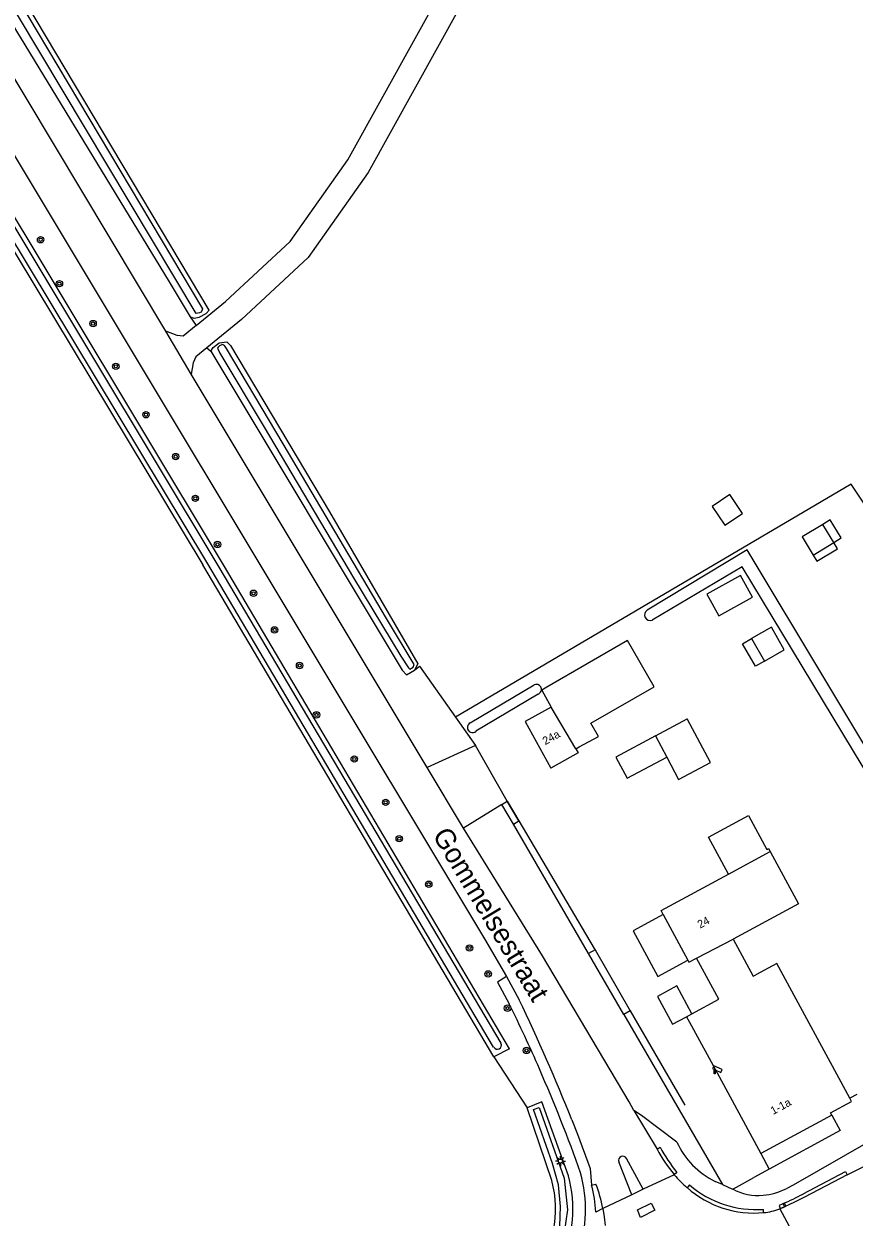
# Model space of a CAD drawing. Extents: x 137000 to 140001, y 403500 to 406000.
# Drawn here: x 139469.8 to 139573.5, y 403918.5 to 404067.6 of the extents above; entities that cross this region are included whole.
import ezdxf

# ---------------------------------------------------------------- set-up
doc = ezdxf.new("R2010")
doc.units = 0
for name, color, linetype in [('gg-afsc-draadraster', 7, 'Continuous'), ('gg-afsc-erfafscheiding', 7, 'Continuous'), ('gg-afsc-hekwerk', 7, 'Continuous'), ('gg-anno-huisnummerreeks BGT', 7, 'Continuous'), ('gg-anno-openbare ruimte label', 7, 'Continuous'), ('gg-bbg-bijgebouw', 7, 'Continuous'), ('gg-bbg-gedigitaliseerde bebouwing', 7, 'Continuous'), ('gg-bbg-gedigitaliseerde bijgebouw', 7, 'Continuous'), ('gg-bbg-hoofdgebouw', 7, 'Continuous'), ('gg-bbg-luifel en loopbrug', 7, 'Continuous'), ('gg-bbg-tussenscheiding', 7, 'Continuous'), ('gg-knt-bronhoudergrens', 7, 'Continuous'), ('gg-knt-onverhard', 7, 'Continuous'), ('gg-knt-verharding', 7, 'Continuous'), ('gg-knt-verharding nz', 7, 'Continuous'), ('gg-kntw-bovenkant insteek waterloop', 7, 'Continuous'), ('gg-kntw-waterlijn', 7, 'Continuous'), ('gt-grn-groengrens NZ', 7, 'Continuous'), ('gt-grn-weggrens', 7, 'Continuous'), ('gt-symb-boom', 7, 'Continuous'), ('gt-symb-camera', 7, 'Continuous'), ('gt-symb-kolk', 7, 'Continuous'), ('gt-symb-lichtmast', 7, 'Continuous')]:
    doc.layers.add(name, color=color, linetype=linetype)

# ---------------------------------------------------------------- blocks, each defined once
blk = doc.blocks.new('gt0-BOOM')
at = {"layer": 'gt-symb-boom'}
for radius in [0.4, 0.2]:
    blk.add_circle((0, 0), radius, dxfattribs=at)
blk = doc.blocks.new('gt0-CAMERA')
at = {"layer": 'gt-symb-camera'}
for points in [[(0.07, 0.48), (0.75, 0.16), (0.92, 0.51), (-0.12, 1), (-0.28, 0.65), (-0.07, 0.55)], [(0.07, 0.48), (0.07, 0), (-0.07, 0), (-0.07, 0.55)]]:
    blk.add_lwpolyline(points, dxfattribs=at)
blk = doc.blocks.new('gt0-KOLK')
at = {"layer": 'gt-symb-kolk'}
blk.add_lwpolyline([(0, 0), (0.37, 0), (0.37, 0.4), (-0.38, 0.4), (-0.38, 0), (0, 0)], dxfattribs=at)
blk = doc.blocks.new('gt0-LMAST')
at = {"layer": 'gt-symb-lichtmast'}
for p, q in [((-0.18, 0.17), (-0.45, 0.44)), ((-0.01, 0.25), (-0.01, 0.62)), ((0.17, 0.17), (0.44, 0.44)), ((-0.26, 0), (-0.63, 0)), ((-0.18, -0.18), (-0.45, -0.45)), ((-0.01, -0.25), (-0.01, -0.63)), ((0.44, -0.45), (0.17, -0.18)), ((0.24, 0), (0.62, 0))]:
    blk.add_line(p, q, dxfattribs=at)
blk.add_circle((-0.01, 0), 0.25, dxfattribs=at)

msp = doc.modelspace()

# ---------------------------------------------------------------- linework, layer by layer
at = {"layer": 'gg-afsc-draadraster'}
msp.add_lwpolyline([(139577.76, 404003.1), (139573.16, 404010.07), (139523.72, 403980.95)], dxfattribs=at)
at = {"layer": 'gg-afsc-erfafscheiding'}
for p, q in [((139519.2, 403987.33), (139523.72, 403980.95)), ((139523.72, 403980.95), (139526.22, 403977.43)), ((139530.15, 403970.45), (139526.22, 403977.43)), ((139531.61, 403967.99), (139541.05, 403952.04)), ((139541.05, 403952.04), (139541.15, 403951.87)), ((139541.15, 403951.87), (139545.54, 403944.26)), ((139545.54, 403944.26), (139544.75, 403943.83)), ((139573.85, 403933.81), (139572.98, 403933.36)), ((139558.8, 403922.26), (139560.98, 403923.44)), ((139562.9, 403924.51), (139560.98, 403923.44)), ((139558.33, 403922.01), (139558.8, 403922.26))]:
    msp.add_line(p, q, dxfattribs=at)
at = {"layer": 'gg-afsc-hekwerk'}
for p, q in [((139530.15, 403970.45), (139531.61, 403967.99)), ((139531.61, 403967.99), (139541.05, 403952.04)), ((139541.05, 403952.04), (139541.15, 403951.87)), ((139541.15, 403951.87), (139545.54, 403944.26)), ((139545.54, 403944.26), (139552.38, 403932.47)), ((139558.8, 403922.26), (139560.98, 403923.44))]:
    msp.add_line(p, q, dxfattribs=at)
at = {"layer": 'gg-bbg-bijgebouw'}
for q in [(139552.66, 403980.73), (139550.11, 403975.96)]:
    msp.add_line((139548.69, 403978.61), q, dxfattribs=at)
for points in [[(139538.73, 403977.01), (139539.17, 403977.25), (139541.56, 403978.55), (139540.61, 403980.2), (139548.51, 403984.75), (139545.19, 403990.51), (139535.11, 403984.71), (139534.47, 403984.34), (139535.65, 403982.21)], [(139550.11, 403975.96), (139551.59, 403973.18), (139555.56, 403975.3), (139552.66, 403980.73)]]:
    msp.add_lwpolyline(points, dxfattribs=at)
at = {"layer": 'gg-bbg-gedigitaliseerde bebouwing'}
msp.add_line((139557.8, 403961.34), (139563.02, 403964.17), dxfattribs=at)
at = {"layer": 'gg-bbg-gedigitaliseerde bijgebouw'}
for p, q in [((139570.97, 404002.78), (139569.59, 404005.04)), ((139568.38, 404001.21), (139570.97, 404002.78)), ((139560.68, 403990.76), (139562.3, 403987.94)), ((139562.3, 403987.94), (139564.79, 403989.37))]:
    msp.add_line(p, q, dxfattribs=at)
for points in [[(139569.59, 404005.04), (139567.01, 404003.47), (139568.38, 404001.21)], [(139560.82, 403995.95), (139559.3, 403998.66), (139555.11, 403996.32), (139556.62, 403993.6), (139560.82, 403995.95)], [(139564.79, 403989.37), (139563.18, 403992.18), (139560.68, 403990.76)]]:
    msp.add_lwpolyline(points, dxfattribs=at)
at = {"layer": 'gg-bbg-hoofdgebouw'}
for p, q in [((139549.65, 403956.3), (139552.74, 403950.58)), ((139552.59, 403943.54), (139553.24, 403943.89)), ((139556.65, 403936.05), (139561.85, 403926.44)), ((139570.73, 403931.25), (139561.85, 403926.44))]:
    msp.add_line(p, q, dxfattribs=at)
for points in [[(139535.65, 403982.21), (139532.39, 403980.41), (139535.6, 403974.6)], [(139538.73, 403977.01), (139539.02, 403976.48), (139535.6, 403974.6)], [(139563.02, 403964.17), (139566.55, 403957.63), (139558.42, 403953.22)], [(139549.65, 403956.3), (139549.39, 403956.79), (139557.8, 403961.34)], [(139558.42, 403953.22), (139560.92, 403948.61), (139561.22, 403948.78)], [(139552.74, 403950.58), (139552.88, 403950.33), (139553.84, 403950.85)], [(139553.24, 403943.89), (139556.61, 403945.72), (139553.84, 403950.85)], [(139572.98, 403933.36), (139563.86, 403950.2), (139561.22, 403948.78)], [(139552.59, 403943.54), (139552.95, 403942.87), (139556.65, 403936.05)], [(139570.73, 403931.25), (139570.58, 403931.54), (139573.2, 403932.96), (139572.98, 403933.36)]]:
    msp.add_lwpolyline(points, dxfattribs=at)
at = {"layer": 'gg-bbg-luifel en loopbrug'}
msp.add_line((139561.85, 403926.44), (139562.9, 403924.51), dxfattribs=at)
for points in [[(139557.99, 404008.76), (139555.79, 404007.28), (139557.36, 404004.93), (139559.57, 404006.41), (139557.99, 404008.76)], [(139570.97, 404002.78), (139571.89, 404003.34), (139570.52, 404005.6), (139569.59, 404005.04)], [(139568.38, 404001.21), (139568.85, 404000.43), (139571.44, 404002), (139570.97, 404002.78)], [(139562.3, 403987.94), (139561.19, 403987.31), (139559.58, 403990.12), (139560.68, 403990.76)], [(139548.69, 403978.61), (139543.75, 403975.97), (139545.17, 403973.32), (139550.11, 403975.96)], [(139557.8, 403961.34), (139555.31, 403965.95), (139560.33, 403968.67), (139562.61, 403964.44), (139562.81, 403964.55), (139563.02, 403964.17)], [(139549.65, 403956.3), (139545.89, 403954.26), (139548.98, 403948.54), (139552.74, 403950.58)], [(139553.24, 403943.89), (139551.35, 403947.38), (139548.94, 403946.08), (139550.83, 403942.59), (139552.59, 403943.54)], [(139570.73, 403931.25), (139571.78, 403929.31), (139562.9, 403924.51)]]:
    msp.add_lwpolyline(points, dxfattribs=at)
at = {"layer": 'gg-bbg-tussenscheiding'}
for p, q in [((139538.73, 403977.01), (139535.65, 403982.21)), ((139553.84, 403950.85), (139558.42, 403953.22))]:
    msp.add_line(p, q, dxfattribs=at)
at = {"layer": 'gg-knt-bronhoudergrens'}
msp.add_line((139528.48, 403938.53), (139532.66, 403932.17), dxfattribs=at)
at = {"layer": 'gg-knt-onverhard'}
for points in [[(139491.29, 404029.87), (139494.97, 404032.89), (139503.02, 404040.36), (139510.26, 404050.58), (139527.49, 404081.69), (139540.58, 404106.68), (139553.04, 404125.36), (139568.03, 404138.11), (139589.58, 404152.78), (139603.6, 404158.75), (139631.51, 404167.9), (139632.52, 404165.07), (139604.66, 404155.94), (139589.5, 404149.48), (139589.47, 404144.47), (139591.17, 404139.97), (139612.78, 404114.78), (139639.17, 404074.78), (139665.44, 404031.24), (139674.74, 404017.1), (139677, 404013.66), (139684.57, 404000.24)], [(139672.1, 404015.65), (139662.9, 404029.64), (139636.63, 404073.18), (139610.38, 404112.97), (139588.9, 404138.01), (139584.48, 404139.45), (139577.11, 404140.66), (139569.85, 404135.72), (139555.3, 404123.34), (139543.16, 404105.15), (139530.13, 404080.27), (139512.8, 404048.98), (139505.28, 404038.37), (139496.94, 404030.62), (139492.61, 404027.08)], [(139491.29, 404029.87), (139489.68, 404028.56), (139488.93, 404028.61), (139487.48, 404029.17)], [(139492.61, 404027.08), (139491.25, 404025.97), (139490.9, 404025.22), (139490.68, 404023.82)]]:
    msp.add_lwpolyline(points, dxfattribs=at)
at = {"layer": 'gg-knt-verharding'}
for p, q in [((139487.48, 404029.17), (139381.92, 404205.17)), ((139520.18, 403974.65), (139490.68, 404023.82)), ((139524.71, 403967.09), (139520.18, 403974.65)), ((139529.48, 403970.06), (139524.71, 403967.09)), ((139529.48, 403970.06), (139530.15, 403970.45)), ((139530.93, 403967.59), (139529.48, 403970.06)), ((139531.61, 403967.99), (139530.15, 403970.45)), ((139530.93, 403967.59), (139531.61, 403967.99)), ((139540.34, 403951.45), (139530.93, 403967.59)), ((139544.75, 403943.83), (139540.34, 403951.45)), ((139530.08, 403948.55), (139531.66, 403945.65)), ((139544.75, 403943.83), (139557.06, 403922.57)), ((139545.97, 403931.83), (139548.89, 403927)), ((139548.89, 403927), (139549.27, 403927.23)), ((139545.72, 403921.3), (139544.12, 403925.4)), ((139547.16, 403922), (139545.08, 403925.82)), ((139551.37, 403924.09), (139551.04, 403923.8)), ((139540.7, 403922.48), (139541.25, 403922.62)), ((139547.16, 403922), (139545.72, 403921.3)), ((139552.94, 403922.52), (139552.67, 403922.18)), ((139557.06, 403922.57), (139556.17, 403922.95)), ((139557.06, 403922.57), (139558.33, 403922.01)), ((139564.62, 403920.19), (139564.81, 403919.79)), ((139542.11, 403919.57), (139541.25, 403919.14)), ((139562.21, 403919.07), (139562.2, 403919.47)), ((139564.81, 403919.79), (139564.23, 403919.54))]:
    msp.add_line(p, q, dxfattribs=at)
for points in [[(139456.55, 404071.12), (139527.32, 403953.26), (139530.08, 403948.55)], [(139530.08, 403948.55), (139528.95, 403947.86), (139530.42, 403945.16)], [(139572.65, 403923.79), (139576.85, 403925.9), (139587.84, 403931.5), (139601.46, 403939.44)], [(139538.23, 403930.64), (139538.93, 403928.86), (139540.52, 403924.57), (139540.7, 403922.48)], [(139551.36, 403927.87), (139546.93, 403931.19), (139545.97, 403931.83)], [(139579.88, 403930.54), (139575.57, 403928.04), (139565.89, 403922.48), (139565.01, 403922.05)], [(139572.65, 403923.79), (139567.31, 403920.98), (139566.08, 403920.35), (139564.81, 403919.79)], [(139567.14, 403921.39), (139572.45, 403924.19), (139572.65, 403923.79)], [(139546.81, 403918.45), (139546.44, 403919.43), (139548.14, 403920.23), (139548.62, 403919.36), (139546.81, 403918.45)], [(139542.11, 403919.57), (139542.28, 403918.52), (139542.39, 403917.46)]]:
    msp.add_lwpolyline(points, dxfattribs=at)
for centre, radius, start, end in [((139331.39, 403848.96), 222.39, 21.5499, 25.7713), ((139348.32, 403855.73), 202.87, 23.6188, 26.1552), ((139348.25, 403855.68), 202.95, 19.6849, 23.6235), ((139560.62, 403932.12), 10.19, 204.6309, 244.1091), ((139544.61, 403925.59), 0.524, 26.6523, 201.2394), ((139564.89, 403935.44), 18.09, 207.8079, 220.0261), ((139568.68, 403937.93), 22.16, 208.8658, 218.6489), ((139522.57, 403919.43), 17.39, 341.4807, 15.3768), ((139560.41, 403931.58), 12.18, 219.6864, 230.5249), ((139523.16, 403917.9), 18.13, 3.9141, 14.6495), ((139523.83, 403916.09), 18.61, 10.7874, 20.557), ((139561.04, 403931.64), 12.63, 228.4998, 275.3344), ((139561.28, 403932.23), 12.79, 229.3579, 274.1255), ((139561.59, 403928.14), 6.94, 241.9551, 274.7482), ((139561.31, 403929.51), 8.33, 275.8731, 296.3892), ((139555.52, 403942.57), 24.16, 292.1209, 298.7547), ((139561.73, 403925.62), 6.57, 274.1831, 292.377)]:
    msp.add_arc(centre, radius, start, end, dxfattribs=at)
at = {"layer": 'gg-knt-verharding nz'}
msp.add_lwpolyline([(139545.97, 403931.83), (139545.39, 403932.92), (139534.58, 403951.15), (139524.71, 403967.09)], dxfattribs=at)
at = {"layer": 'gg-kntw-bovenkant insteek waterloop'}
for p, q in [((139452.67, 404065.45), (139492.11, 404000)), ((139528.48, 403938.53), (139492.11, 404000)), ((139525.55, 403980.26), (139533.53, 403984.99)), ((139534.02, 403983.83), (139526.26, 403979.19)), ((139530.47, 403939.54), (139528.48, 403938.53)), ((139535.73, 403923.08), (139532.66, 403932.17))]:
    msp.add_line(p, q, dxfattribs=at)
for points in [[(139386.87, 404206.06), (139386.78, 404206), (139386.25, 404205.41), (139386.17, 404204.42), (139417.02, 404153.17), (139447.37, 404101.81), (139487.93, 404035.35), (139490.55, 404030.97)], [(139490.55, 404030.97), (139491.02, 404030.78), (139491.65, 404030.91), (139492.52, 404031.39), (139492.92, 404031.81), (139456.9, 404092.22)], [(139530.47, 403939.54), (139494.69, 404000), (139454.45, 404066.89)], [(139493.12, 404026.68), (139493.4, 404027.11), (139494.18, 404027.72), (139495.12, 404027.82), (139495.57, 404027.36), (139507.95, 404006.6), (139518.99, 403987.61), (139518.59, 403986.83)], [(139493.12, 404026.68), (139517.04, 403986.82), (139517.59, 403986.25), (139518.59, 403986.83)], [(139579.69, 403969.33), (139560.14, 404001.85), (139547.64, 403994.32)], [(139578.38, 403968.51), (139559.51, 403999.74), (139548.3, 403993.09)], [(139537.82, 403923.65), (139534.51, 403932.92), (139532.66, 403932.17)]]:
    msp.add_lwpolyline(points, dxfattribs=at)
for centre, radius, start, end in [((139548.03, 403993.73), 0.701, 123.8563, 292.6895), ((139533.81, 403984.42), 0.633, 30.014, 116.7011), ((139533.81, 403984.43), 0.632, 289.3588, 29.8188), ((139525.83, 403979.67), 0.649, 115.7437, 311.933), ((139522.52, 403919.48), 15.86, 335.0938, 15.2399), ((139522.52, 403919.48), 13.69, 322.3178, 15.2373)]:
    msp.add_arc(centre, radius, start, end, dxfattribs=at)
at = {"layer": 'gg-kntw-waterlijn'}
for points in [[(139388.79, 404205.11), (139388.51, 404204.55), (139394.25, 404195.63), (139415.86, 404159.33), (139426.22, 404142.34), (139446.98, 404107.72), (139471.44, 404066.61), (139492.1, 404031.98), (139492.05, 404031.82), (139491.91, 404031.55), (139491.71, 404031.45), (139491.27, 404031.39), (139452.28, 404096.48), (139445.13, 404108.88), (139419.89, 404150.83), (139413.42, 404161.09)], [(139528.47, 403939.74), (139492.63, 404000.31), (139453.53, 404065.14)], [(139529.39, 403940.21), (139494.18, 403999.69), (139454.45, 404065.68)], [(139494.59, 404027.49), (139494.21, 404027.35), (139494.03, 404027.19), (139493.95, 404027.03), (139494.25, 404026.43), (139499.79, 404017.18), (139510.96, 403998.37), (139516.85, 403988.59), (139517.82, 403987.1), (139517.99, 403986.93), (139518.43, 403987.2), (139518.55, 403987.55), (139515.06, 403993.29), (139502.18, 404015.09), (139495.07, 404027.01), (139494.82, 404027.38), (139494.59, 404027.49)], [(139499.5, 403891.1), (139509.03, 403895.84), (139530.08, 403907.47), (139532.22, 403908.97), (139534.39, 403911.34), (139536, 403914.63), (139536.73, 403917.39), (139536.83, 403919.83), (139536.59, 403922.54), (139535.83, 403925.19), (139533.45, 403931.96), (139534.16, 403932.21), (139537.27, 403923.38), (139537.68, 403919.4), (139537.3, 403916.6), (139536.63, 403914.07), (139534.98, 403910.73), (139532.95, 403908.4), (139525.18, 403903.79), (139509.94, 403895.55), (139499.83, 403890.32), (139499.5, 403891.1)]]:
    msp.add_lwpolyline(points, dxfattribs=at)
msp.add_arc((139528.93, 403939.98), 0.511, 206.9892, 26.8424, dxfattribs=at)
at = {"layer": 'gt-grn-groengrens NZ'}
for p, q in [((139490.55, 404030.97), (139491.29, 404029.87)), ((139492.61, 404027.08), (139493.12, 404026.68)), ((139518.59, 403986.83), (139519.2, 403987.33)), ((139541.15, 403951.87), (139540.34, 403951.45))]:
    msp.add_line(p, q, dxfattribs=at)
at = {"layer": 'gt-grn-weggrens'}
for p, q in [((139490.68, 404023.82), (139487.48, 404029.17)), ((139526.22, 403977.43), (139520.18, 403974.65)), ((139551.04, 403923.8), (139547.16, 403922)), ((139545.72, 403921.3), (139542.11, 403919.57)), ((139564.23, 403919.54), (139565.99, 403916.28))]:
    msp.add_line(p, q, dxfattribs=at)

# ---------------------------------------------------------------- block references
at = {"layer": 'gt-symb-boom'}
for p in [(139471.85, 404040.59), (139474.2, 404035.1), (139478.41, 404030.12), (139481.25, 404024.78), (139485.02, 404018.73), (139488.73, 404013.51), (139491.19, 404008.29), (139493.96, 404002.53), (139498.46, 403996.43), (139501.09, 403991.85), (139504.21, 403987.41), (139506.33, 403981.24), (139511.05, 403975.73), (139514.98, 403970.32), (139516.67, 403965.77), (139520.36, 403960.08), (139525.45, 403952.12), (139527.78, 403948.88), (139530.2, 403944.6), (139532.57, 403939.32)]:
    msp.add_blockref('gt0-BOOM', p, dxfattribs=at)
at = {"layer": 'gt-symb-camera'}
msp.add_blockref('gt0-CAMERA', (139556.1, 403936.42), dxfattribs=at)
at = {"layer": 'gt-symb-kolk', "rotation": 23.015280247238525}
msp.add_blockref('gt0-KOLK', (139564.64, 403919.72), dxfattribs=at)
at = {"layer": 'gt-symb-lichtmast'}
msp.add_blockref('gt0-LMAST', (139536.82, 403925.51), dxfattribs=at)

# ---------------------------------------------------------------- texts
at = {"layer": 'gg-anno-huisnummerreeks BGT'}
for s, rotation, p in [('24a', 28.9, (139534.92, 403977.45)), ('24', 28.4, (139554.27, 403954.53)), ('1-1a', 28.4, (139563.4, 403931.26))]:
    msp.add_text(s, height=1, rotation=rotation, dxfattribs=at).set_placement(p)
at = {"layer": 'gg-anno-openbare ruimte label'}
msp.add_text('Gommelsestraat', height=2.5, rotation=301, dxfattribs=at).set_placement((139520.76, 403966.22))

doc.saveas('drawing.dxf')
